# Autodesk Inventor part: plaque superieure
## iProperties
Author: chr
Shininess: 20.0
PropertySet Name: _Private Model Information
Length Units: 11269
Angle Units: 11286
Time Units: 11279
Mass Units: 11290
Length Display Precision: 3
Angle Display Precision: 2
Compacted: False
Created: 2001-06
Part Number: plaque superieure
Material: Par défaut
Document SubType Name: Modélisation
Designer: chr
Control State: 0
Master: False
Checked Out: False
PropertySet Name: Design Tracking Control
Density: 0.0
Volumn: 0.0
Area: 0.0
PropertySet Name: Model Information
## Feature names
1. Extrusion1
2. Extrusion2
3. Perçage1 [Hole]
4. Congé1 [Fillet]
5. Congé2 [Fillet]
6. Extrusion4
7. Perçage2 [Hole]
8. Extrusion5
9. Perçage3 [Hole]
10. Perçage4 [Hole]
11. Extrusion6
